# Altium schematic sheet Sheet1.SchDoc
size A; SheetNumber: 1; SheetTotal: 1
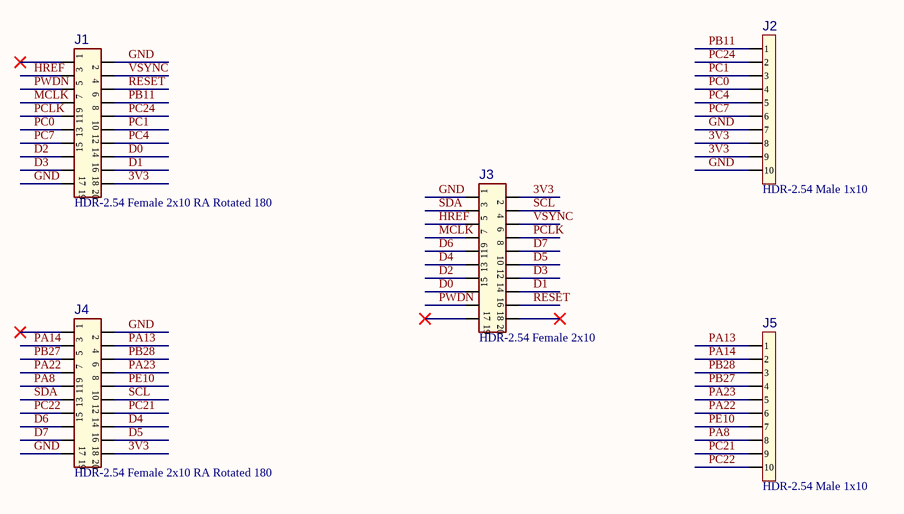
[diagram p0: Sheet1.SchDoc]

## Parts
J1  value HDR-2.54 Female 2x10 RA Rotated 180  [HDR_F_2.54_2x10_RA_180]  (hidden comment: Header 2x10)
J2  value HDR-2.54 Male 1x10  [HDR_M_2.54_1x10]  (hidden comment: Header 1x10)
J3  value HDR-2.54 Female 2x10  [HDR_F_2.54_2x10_SFH11-PBPC-D10-ST-BK]  (hidden comment: Header 2x10)
J4  value HDR-2.54 Female 2x10 RA Rotated 180  [HDR_F_2.54_2x10_RA_180]  (hidden comment: Header 2x10)
J5  value HDR-2.54 Male 1x10  [HDR_M_2.54_1x10]  (hidden comment: Header 1x10)

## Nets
3V3: J1.20 J2.8 J2.9 J3.2 J4.20
D0: J1.16 J3.15
D1: J1.18 J3.16
D2: J1.15 J3.13
D3: J1.17 J3.14
D4: J3.11 J4.16
D5: J3.12 J4.18
D6: J3.9 J4.15
D7: J3.10 J4.17
GND: J1.2 J1.19 J2.7 J2.10 J3.1 J4.2 J4.19
HREF: J1.3 J3.5
MCLK: J1.7 J3.7
PA8: J4.9 J5.8
PA13: J4.4 J5.1
PA14: J4.3 J5.2
PA22: J4.7 J5.6
PA23: J4.8 J5.5
PB11: J1.8 J2.1
PB27: J4.5 J5.4
PB28: J4.6 J5.3
PC0: J1.11 J2.4
PC1: J1.12 J2.3
PC4: J1.14 J2.5
PC7: J1.13 J2.6
PC21: J4.14 J5.9
PC22: J4.13 J5.10
PC24: J1.10 J2.2
PCLK: J1.9 J3.8
PE10: J4.10 J5.7
PWDN: J1.5 J3.17
RESET: J1.6 J3.18
SCL: J3.4 J4.12
SDA: J3.3 J4.11
VSYNC: J1.4 J3.6

Not connected (* = marked no-connect by the designer): J1 1*; J3 19* 20*; J4 1*

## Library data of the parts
J1 J4 = CON1532: Manufacturer 1: Sullins Connector Solutions; Manufacturer Part Number 1: PPPC102LJBN-RC; Description_: CON HDR-2.54 Female 2x10 Rotated 180Degrees Gold TH RT ANGLE; Dev Tools Status: Production; Owner: Jamus Griego; Populated: YES; Restricted Sourcing: No
J2 J5 = CON0105: Manufacturer 1: Aceconn Technology (Shenzhen); Manufacturer Part Number 1: GPHA101-1002A001B1BA; Description_: CON HDR-2.54 Male 1x10 Gold 5.84MH TH VERT; Dev Tools Status: Production; Populated: Yes; Restricted Sourcing: No
J3 = CON1763: Manufacturer 1: Sullins Connector Solutions; Manufacturer Part Number 1: SFH11-PBPC-D10-ST-BK; Description_: CON HDR-2.54 Female 2x10 Gold TH; Dev Tools Status: Production; Owner: Dragos Danaila; Voltage: 1000VAC; Current: 3A; Populated: YES; Restricted Sourcing: No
